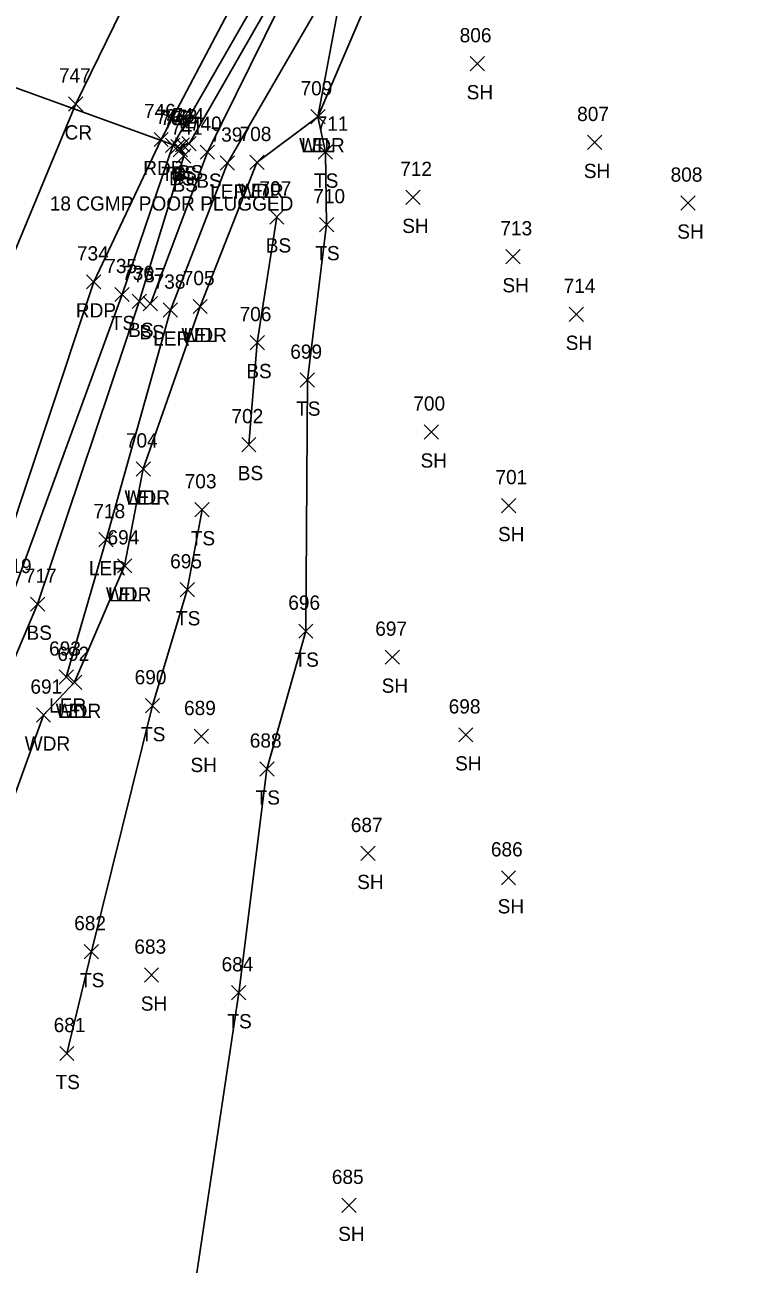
# Model space of a CAD drawing. Extents: x 1586965 to 1590952, y 716317 to 720029.
# Drawn here: x 1587202.1 to 1587304.9, y 719388.4 to 719562.4 of the extents above; entities that cross this region are included whole.
import ezdxf

# ---------------------------------------------------------------- set-up
doc = ezdxf.new("R2010")
doc.units = 0
for name, color, linetype in [('D_A', 7, 'Continuous'), ('D_C', 7, 'Continuous'), ('D_I', 7, 'Continuous'), ('D_TIC', 7, 'Continuous'), ('DCP', 7, 'Continuous'), ('L_A', 7, 'Continuous'), ('L_I', 7, 'Continuous'), ('L_TIC', 7, 'Continuous'), ('LARO', 7, 'Continuous'), ('LAWA', 7, 'Continuous'), ('LELB', 7, 'Continuous'), ('P_A', 7, 'Continuous'), ('P_I', 7, 'Continuous'), ('P_TIC', 7, 'Continuous'), ('PET', 7, 'Continuous'), ('PRC', 7, 'Continuous')]:
    doc.layers.add(name, color=color, linetype=linetype)

msp = doc.modelspace()

# ---------------------------------------------------------------- linework, layer by layer
at = {"layer": 'D_TIC'}
for points in [[(1587222.53, 719544.3), (1587224.53, 719546.3)], [(1587224.53, 719544.3), (1587222.53, 719546.3)]]:
    msp.add_lwpolyline(points, dxfattribs=at)
at = {"layer": 'DCP'}
msp.add_lwpolyline([(1587223.53, 719545.3), (1587183.87, 719559.68)], dxfattribs=at)
at = {"layer": 'L_TIC'}
for points in [[(1587264.55, 719555.92), (1587266.55, 719557.92)], [(1587266.55, 719555.92), (1587264.55, 719557.92)], [(1587242.18, 719548.48), (1587244.18, 719550.48)], [(1587244.18, 719548.48), (1587242.18, 719550.48)], [(1587242.18, 719548.48), (1587244.18, 719550.48)], [(1587244.18, 719548.48), (1587242.18, 719550.48)], [(1587221.82, 719544.46), (1587223.82, 719546.46)], [(1587223.82, 719544.46), (1587221.82, 719546.46)], [(1587222.87, 719543.83), (1587224.87, 719545.83)], [(1587224.87, 719543.83), (1587222.87, 719545.83)], [(1587223.18, 719544.53), (1587225.18, 719546.53)], [(1587225.18, 719544.53), (1587223.18, 719546.53)], [(1587224.1, 719544.69), (1587226.1, 719546.69)], [(1587226.1, 719544.69), (1587224.1, 719546.69)], [(1587280.98, 719544.87), (1587282.98, 719546.87)], [(1587282.98, 719544.87), (1587280.98, 719546.87)], [(1587223.35, 719542.95), (1587225.35, 719544.95)], [(1587225.35, 719542.95), (1587223.35, 719544.95)], [(1587226.67, 719543.5), (1587228.67, 719545.5)], [(1587228.67, 719543.5), (1587226.67, 719545.5)], [(1587229.49, 719541.98), (1587231.49, 719543.98)], [(1587231.49, 719541.98), (1587229.49, 719543.98)], [(1587233.63, 719542.06), (1587235.63, 719544.06)], [(1587235.63, 719542.06), (1587233.63, 719544.06)], [(1587233.63, 719542.06), (1587235.63, 719544.06)], [(1587235.63, 719542.06), (1587233.63, 719544.06)], [(1587243.22, 719543.51), (1587245.22, 719545.51)], [(1587245.22, 719543.51), (1587243.22, 719545.51)], [(1587255.51, 719537.16), (1587257.51, 719539.16)], [(1587257.51, 719537.16), (1587255.51, 719539.16)], [(1587294.09, 719536.36), (1587296.09, 719538.36)], [(1587296.09, 719536.36), (1587294.09, 719538.36)], [(1587236.42, 719534.42), (1587238.42, 719536.42)], [(1587238.42, 719534.42), (1587236.42, 719536.42)], [(1587243.4, 719533.33), (1587245.4, 719535.33)], [(1587245.4, 719533.33), (1587243.4, 719535.33)], [(1587269.56, 719528.83), (1587271.56, 719530.83)], [(1587271.56, 719528.83), (1587269.56, 719530.83)], [(1587214.71, 719523.53), (1587216.71, 719525.53)], [(1587216.71, 719523.53), (1587214.71, 719525.53)], [(1587217.12, 719522.56), (1587219.12, 719524.56)], [(1587219.12, 719522.56), (1587217.12, 719524.56)], [(1587218.68, 719522.24), (1587220.68, 719524.24)], [(1587220.68, 719522.24), (1587218.68, 719524.24)], [(1587221.49, 719521.34), (1587223.49, 719523.34)], [(1587223.49, 719521.34), (1587221.49, 719523.34)], [(1587225.66, 719521.84), (1587227.66, 719523.84)], [(1587227.66, 719521.84), (1587225.66, 719523.84)], [(1587225.66, 719521.84), (1587227.66, 719523.84)], [(1587227.66, 719521.84), (1587225.66, 719523.84)], [(1587278.44, 719520.75), (1587280.44, 719522.75)], [(1587280.44, 719520.75), (1587278.44, 719522.75)], [(1587233.68, 719516.78), (1587235.68, 719518.78)], [(1587235.68, 719516.78), (1587233.68, 719518.78)], [(1587240.71, 719511.51), (1587242.71, 719513.51)], [(1587242.71, 719511.51), (1587240.71, 719513.51)], [(1587258.08, 719504.23), (1587260.08, 719506.23)], [(1587260.08, 719504.23), (1587258.08, 719506.23)], [(1587232.49, 719502.46), (1587234.49, 719504.46)], [(1587234.49, 719502.46), (1587232.49, 719504.46)], [(1587217.68, 719499.05), (1587219.68, 719501.05)], [(1587219.68, 719499.05), (1587217.68, 719501.05)], [(1587217.68, 719499.05), (1587219.68, 719501.05)], [(1587219.68, 719499.05), (1587217.68, 719501.05)], [(1587225.93, 719493.32), (1587227.93, 719495.32)], [(1587227.93, 719493.32), (1587225.93, 719495.32)], [(1587268.95, 719493.9), (1587270.95, 719495.9)], [(1587270.95, 719493.9), (1587268.95, 719495.9)], [(1587212.47, 719489.13), (1587214.47, 719491.13)], [(1587214.47, 719489.13), (1587212.47, 719491.13)], [(1587215.07, 719485.45), (1587217.07, 719487.45)], [(1587217.07, 719485.45), (1587215.07, 719487.45)], [(1587215.07, 719485.45), (1587217.07, 719487.45)], [(1587217.07, 719485.45), (1587215.07, 719487.45)], [(1587223.86, 719482.09), (1587225.86, 719484.09)], [(1587225.86, 719482.09), (1587223.86, 719484.09)], [(1587202.86, 719480.06), (1587204.86, 719482.06)], [(1587204.86, 719480.06), (1587202.86, 719482.06)], [(1587240.48, 719476.28), (1587242.48, 719478.28)], [(1587242.48, 719476.28), (1587240.48, 719478.28)], [(1587252.63, 719472.63), (1587254.63, 719474.63)], [(1587254.63, 719472.63), (1587252.63, 719474.63)], [(1587206.88, 719469.84), (1587208.88, 719471.84)], [(1587208.88, 719469.84), (1587206.88, 719471.84)], [(1587208.04, 719469.1), (1587210.04, 719471.1)], [(1587210.04, 719469.1), (1587208.04, 719471.1)], [(1587208.04, 719469.1), (1587210.04, 719471.1)], [(1587210.04, 719469.1), (1587208.04, 719471.1)], [(1587218.97, 719465.82), (1587220.97, 719467.82)], [(1587220.97, 719465.82), (1587218.97, 719467.82)], [(1587203.69, 719464.5), (1587205.69, 719466.5)], [(1587205.69, 719464.5), (1587203.69, 719466.5)], [(1587225.81, 719461.5), (1587227.81, 719463.5)], [(1587227.81, 719461.5), (1587225.81, 719463.5)], [(1587262.93, 719461.72), (1587264.93, 719463.72)], [(1587264.93, 719461.72), (1587262.93, 719463.72)], [(1587235.03, 719456.93), (1587237.03, 719458.93)], [(1587237.03, 719456.93), (1587235.03, 719458.93)], [(1587249.2, 719445.08), (1587251.2, 719447.08)], [(1587251.2, 719445.08), (1587249.2, 719447.08)], [(1587268.91, 719441.66), (1587270.91, 719443.66)], [(1587270.91, 719441.66), (1587268.91, 719443.66)], [(1587210.4, 719431.3), (1587212.4, 719433.3)], [(1587212.4, 719431.3), (1587210.4, 719433.3)], [(1587218.84, 719428.01), (1587220.84, 719430.01)], [(1587220.84, 719428.01), (1587218.84, 719430.01)], [(1587231.07, 719425.53), (1587233.07, 719427.53)], [(1587233.07, 719425.53), (1587231.07, 719427.53)], [(1587206.96, 719417), (1587208.96, 719419)], [(1587208.96, 719417), (1587206.96, 719419)], [(1587246.53, 719395.69), (1587248.53, 719397.69)], [(1587248.53, 719395.69), (1587246.53, 719397.69)]]:
    msp.add_lwpolyline(points, dxfattribs=at)
at = {"layer": 'LARO'}
for points in [[(1587207.88, 719470.84), (1587213.47, 719490.13), (1587222.49, 719522.34), (1587230.49, 719542.98), (1587245.4, 719568.76), (1587254.93, 719583.09)], [(1587209.04, 719470.1), (1587216.07, 719486.45), (1587218.68, 719500.05), (1587226.66, 719522.84), (1587234.63, 719543.06), (1587243.18, 719549.48), (1587246.56, 719567.69), (1587254.93, 719583.09)]]:
    msp.add_lwpolyline(points, dxfattribs=at)
at = {"layer": 'LAWA'}
msp.add_lwpolyline([(1587171.91, 719364.5), (1587185.92, 719394.62), (1587194.51, 719437.33), (1587204.69, 719465.5), (1587209.04, 719470.1), (1587216.07, 719486.45), (1587218.68, 719500.05), (1587226.66, 719522.84), (1587234.63, 719543.06), (1587243.18, 719549.48), (1587251, 719567.85), (1587260.43, 719579.32), (1587269.2, 719595.73), (1587274.23, 719603.67), (1587301.03, 719598.43), (1587318.82, 719602.47), (1587334.94, 719606.57), (1587351.65, 719607.7), (1587367.28, 719615.21), (1587401.27, 719626.51), (1587435.01, 719634.6)], dxfattribs=at)
at = {"layer": 'LELB'}
for points in [[(1587111.95, 719287.48), (1587133.61, 719303.61), (1587148.92, 719323.42), (1587167.88, 719366.46), (1587179.01, 719397.6), (1587173.15, 719399.12), (1587186.97, 719441.05), (1587200.36, 719482.43), (1587215.71, 719524.53), (1587222.82, 719545.46), (1587239.38, 719574.3), (1587247.92, 719589.42), (1587267.49, 719614.08), (1587286.95, 719636.16), (1587313.61, 719660.46), (1587335.34, 719679.69), (1587361.68, 719697.91), (1587398.24, 719722.21), (1587438.94, 719742.74)], [(1587111.95, 719287.48), (1587133.61, 719303.61), (1587148.92, 719323.42), (1587167.88, 719366.46), (1587179.01, 719397.6), (1587173.15, 719399.12), (1587186.97, 719441.05), (1587200.36, 719482.43), (1587215.71, 719524.53), (1587222.82, 719545.46), (1587239.38, 719574.3), (1587247.92, 719589.42), (1587267.49, 719614.08), (1587286.95, 719636.16), (1587313.61, 719660.46), (1587335.34, 719679.69), (1587361.68, 719697.91), (1587398.24, 719722.21), (1587438.94, 719742.74)], [(1587178.28, 719402.93), (1587189.21, 719440.25), (1587198.32, 719468.09), (1587203.86, 719481.06), (1587218.12, 719523.56), (1587224.35, 719543.95), (1587223.87, 719544.83), (1587224.18, 719545.53), (1587225.1, 719545.69), (1587240.99, 719573.37), (1587249.54, 719588.04), (1587270.51, 719611.5), (1587289.99, 719633.55), (1587315.89, 719657.91), (1587337.85, 719676.76), (1587363.47, 719694.64), (1587400.93, 719718.94), (1587441.36, 719738.52)], [(1587178.28, 719402.93), (1587189.21, 719440.25), (1587198.32, 719468.09), (1587203.86, 719481.06), (1587218.12, 719523.56), (1587224.35, 719543.95), (1587223.87, 719544.83), (1587224.18, 719545.53), (1587225.1, 719545.69), (1587240.99, 719573.37), (1587249.54, 719588.04), (1587270.51, 719611.5), (1587289.99, 719633.55), (1587315.89, 719657.91), (1587337.85, 719676.76), (1587363.47, 719694.64), (1587400.93, 719718.94), (1587441.36, 719738.52)], [(1587219.68, 719523.24), (1587227.67, 719544.5), (1587241.78, 719573.06)], [(1587219.68, 719523.24), (1587227.67, 719544.5), (1587241.78, 719573.06)], [(1587244.22, 719544.51), (1587243.18, 719549.48)], [(1587244.22, 719544.51), (1587243.18, 719549.48)], [(1587190.7, 719286.28), (1587204.26, 719320.17), (1587213.18, 719338.83), (1587223.28, 719367.89), (1587232.07, 719426.53), (1587236.03, 719457.93), (1587241.48, 719477.28), (1587241.71, 719512.51), (1587244.4, 719534.33), (1587244.22, 719544.51)], [(1587190.7, 719286.28), (1587204.26, 719320.17), (1587213.18, 719338.83), (1587223.28, 719367.89), (1587232.07, 719426.53), (1587236.03, 719457.93), (1587241.48, 719477.28), (1587241.71, 719512.51), (1587244.4, 719534.33), (1587244.22, 719544.51)], [(1587233.49, 719503.46), (1587234.68, 719517.78), (1587237.42, 719535.42)], [(1587233.49, 719503.46), (1587234.68, 719517.78), (1587237.42, 719535.42)], [(1587207.96, 719418), (1587211.4, 719432.3), (1587219.97, 719466.82), (1587224.86, 719483.09), (1587226.93, 719494.32)], [(1587207.96, 719418), (1587211.4, 719432.3), (1587219.97, 719466.82), (1587224.86, 719483.09), (1587226.93, 719494.32)]]:
    msp.add_lwpolyline(points, dxfattribs=at)
at = {"layer": 'P_TIC'}
for points in [[(1587208.21, 719550.28), (1587210.21, 719552.28)], [(1587210.21, 719550.28), (1587208.21, 719552.28)], [(1587220.19, 719545.28), (1587222.19, 719547.28)], [(1587222.19, 719545.28), (1587220.19, 719547.28)], [(1587210.74, 719525.3), (1587212.74, 719527.3)], [(1587212.74, 719525.3), (1587210.74, 719527.3)]]:
    msp.add_lwpolyline(points, dxfattribs=at)
at = {"layer": 'PET'}
msp.add_lwpolyline([(1586998.3, 719170.55), (1587031.46, 719201.5), (1587048.24, 719215.72), (1587069.37, 719240.81), (1587083.56, 719258.07), (1587104.56, 719290.21), (1587133.86, 719331.71), (1587155.62, 719372.22), (1587169, 719404.76), (1587183.27, 719443.5), (1587197.56, 719483.83), (1587211.74, 719526.3), (1587221.19, 719546.28), (1587236.84, 719576.04), (1587246.13, 719590.54), (1587264.51, 719616.23), (1587283.97, 719638.96), (1587310.1, 719664.5), (1587332.49, 719682.99), (1587358.98, 719703.31), (1587395.82, 719726.18), (1587435.88, 719747.89)], dxfattribs=at)
at = {"layer": 'PRC'}
msp.add_lwpolyline([(1586989.8, 719181.42), (1587021.35, 719209.83), (1587057.54, 719247.82), (1587093.64, 719295.06), (1587121.6, 719338.75), (1587145.01, 719385.55), (1587156.05, 719410.32), (1587170.73, 719448.3), (1587185.3, 719487.87), (1587199.88, 719528.69), (1587209.21, 719551.28), (1587224.26, 719582.11), (1587235.22, 719599.27), (1587253.6, 719624.57), (1587274.17, 719648.49), (1587299.95, 719674.27), (1587323.51, 719694.22), (1587352.02, 719715.49), (1587388.91, 719738.13), (1587428.57, 719759.37)], dxfattribs=at)
msp.add_lwpolyline([(1586989.8, 719181.42), (1587021.35, 719209.83), (1587057.54, 719247.82), (1587093.64, 719295.06), (1587121.6, 719338.75), (1587145.01, 719385.55), (1587156.05, 719410.32), (1587170.73, 719448.3), (1587185.3, 719487.87), (1587199.88, 719528.69), (1587209.21, 719551.28), (1587224.26, 719582.11), (1587235.22, 719599.27), (1587253.6, 719624.57), (1587274.17, 719648.49), (1587299.95, 719674.27), (1587323.51, 719694.22), (1587352.02, 719715.49), (1587388.91, 719738.13), (1587428.57, 719759.37)], dxfattribs=at)

# ---------------------------------------------------------------- texts
at = {"layer": 'D_A'}
msp.add_text('P', height=2, dxfattribs=at).set_placement((1587222.91, 719540.3))
at = {"layer": 'D_C'}
msp.add_text('18 CGMP POOR PLUGGED', height=2, dxfattribs=at).set_placement((1587205.56, 719536.3))
at = {"layer": 'D_I'}
msp.add_text('750', height=2, dxfattribs=at).set_placement((1587221.08, 719548.3))
at = {"layer": 'L_A'}
for s, p in [('SH', (1587264.04, 719551.92)), ('WDR', (1587240.55, 719544.48)), ('LEL', (1587240.82, 719544.48)), ('TS', (1587221.22, 719540.46)), ('BS', (1587222.62, 719540.53)), ('BS', (1587223.54, 719540.69)), ('SH', (1587280.47, 719540.87)), ('BS', (1587222.31, 719539.83)), ('BS', (1587222.79, 719538.95)), ('BS', (1587226.11, 719539.5)), ('TS', (1587242.63, 719539.51)), ('LER', (1587228.07, 719537.98)), ('WDR', (1587231.99, 719538.06)), ('LEL', (1587232.27, 719538.06)), ('SH', (1587255, 719533.16)), ('SH', (1587293.58, 719532.36)), ('BS', (1587235.86, 719530.42)), ('TS', (1587242.81, 719529.33)), ('SH', (1587269.05, 719524.83)), ('TS', (1587214.12, 719519.53)), ('BS', (1587216.56, 719518.56)), ('BS', (1587218.12, 719518.24)), ('WDR', (1587224.03, 719517.84)), ('LEL', (1587224.3, 719517.84)), ('LER', (1587220.07, 719517.34)), ('SH', (1587277.93, 719516.75)), ('BS', (1587233.13, 719512.78)), ('TS', (1587240.12, 719507.51)), ('SH', (1587257.57, 719500.23)), ('BS', (1587231.93, 719498.46)), ('WDR', (1587216.04, 719495.05)), ('LEL', (1587216.31, 719495.05)), ('SH', (1587268.44, 719489.9)), ('TS', (1587225.34, 719489.32)), ('LER', (1587211.05, 719485.13)), ('WDR', (1587213.43, 719481.45)), ('LEL', (1587213.71, 719481.45)), ('TS', (1587223.27, 719478.09)), ('BS', (1587202.3, 719476.06)), ('TS', (1587239.89, 719472.28)), ('SH', (1587252.12, 719468.63)), ('LER', (1587205.46, 719465.84)), ('WDR', (1587206.4, 719465.1)), ('LEL', (1587206.68, 719465.1)), ('WDR', (1587202.05, 719460.5)), ('TS', (1587218.37, 719461.82)), ('SH', (1587225.3, 719457.5)), ('SH', (1587262.42, 719457.72)), ('TS', (1587234.44, 719452.93)), ('SH', (1587248.68, 719441.08)), ('SH', (1587268.39, 719437.66)), ('TS', (1587209.81, 719427.3)), ('SH', (1587218.33, 719424.01)), ('TS', (1587230.48, 719421.53)), ('TS', (1587206.37, 719413)), ('SH', (1587246.02, 719391.69))]:
    msp.add_text(s, height=2, dxfattribs=at).set_placement(p)
at = {"layer": 'L_I'}
for s, p in [('806', (1587263.06, 719559.92)), ('709', (1587240.74, 719552.48)), ('709', (1587240.74, 719552.48)), ('807', (1587279.54, 719548.87)), ('745', (1587220.45, 719548.46)), ('742', (1587221.5, 719547.83)), ('743', (1587221.82, 719548.53)), ('744', (1587222.74, 719548.69)), ('740', (1587225.22, 719547.5)), ('711', (1587242.99, 719547.51)), ('741', (1587222.55, 719546.95)), ('739', (1587228.12, 719545.98)), ('708', (1587232.19, 719546.06)), ('708', (1587232.19, 719546.06)), ('712', (1587254.72, 719541.16)), ('808', (1587292.65, 719540.36)), ('707', (1587234.98, 719538.42)), ('710', (1587242.52, 719537.33)), ('713', (1587268.77, 719532.83)), ('735', (1587213.35, 719527.53)), ('736', (1587215.7, 719526.56)), ('737', (1587217.32, 719526.24)), ('738', (1587220.13, 719525.34)), ('705', (1587224.22, 719525.84)), ('705', (1587224.22, 719525.84)), ('714', (1587277.65, 719524.75)), ('706', (1587232.19, 719520.78)), ('699', (1587239.3, 719515.51)), ('700', (1587256.56, 719508.23)), ('702', (1587231.05, 719506.46)), ('704', (1587216.24, 719503.05)), ('704', (1587216.24, 719503.05)), ('703', (1587224.49, 719497.32)), ('701', (1587268.08, 719497.9)), ('718', (1587211.68, 719493.13)), ('694', (1587213.66, 719489.45)), ('694', (1587213.66, 719489.45)), ('719', (1587198.55, 719485.43)), ('695', (1587222.45, 719486.09)), ('717', (1587202.07, 719484.06)), ('696', (1587239.02, 719480.28)), ('697', (1587251.22, 719476.63)), ('693', (1587205.47, 719473.84)), ('692', (1587206.63, 719473.1)), ('692', (1587206.63, 719473.1)), ('690', (1587217.47, 719469.82)), ('691', (1587202.85, 719468.5)), ('689', (1587224.4, 719465.5)), ('698', (1587261.52, 719465.72)), ('688', (1587233.62, 719460.93)), ('687', (1587247.79, 719449.08)), ('686', (1587267.44, 719445.66)), ('682', (1587208.99, 719435.3)), ('683', (1587217.43, 719432.01)), ('684', (1587229.66, 719429.53)), ('681', (1587206.11, 719421)), ('685', (1587245.13, 719399.69))]:
    msp.add_text(s, height=2, dxfattribs=at).set_placement(p)
at = {"layer": 'P_A'}
for s, p in [('CR', (1587207.64, 719546.28)), ('RDP', (1587218.68, 719541.28)), ('RDP', (1587209.22, 719521.3))]:
    msp.add_text(s, height=2, dxfattribs=at).set_placement(p)
at = {"layer": 'P_I'}
for s, p in [('747', (1587206.85, 719554.28)), ('746', (1587218.77, 719549.28)), ('734', (1587209.37, 719529.3))]:
    msp.add_text(s, height=2, dxfattribs=at).set_placement(p)

doc.saveas('drawing.dxf')
